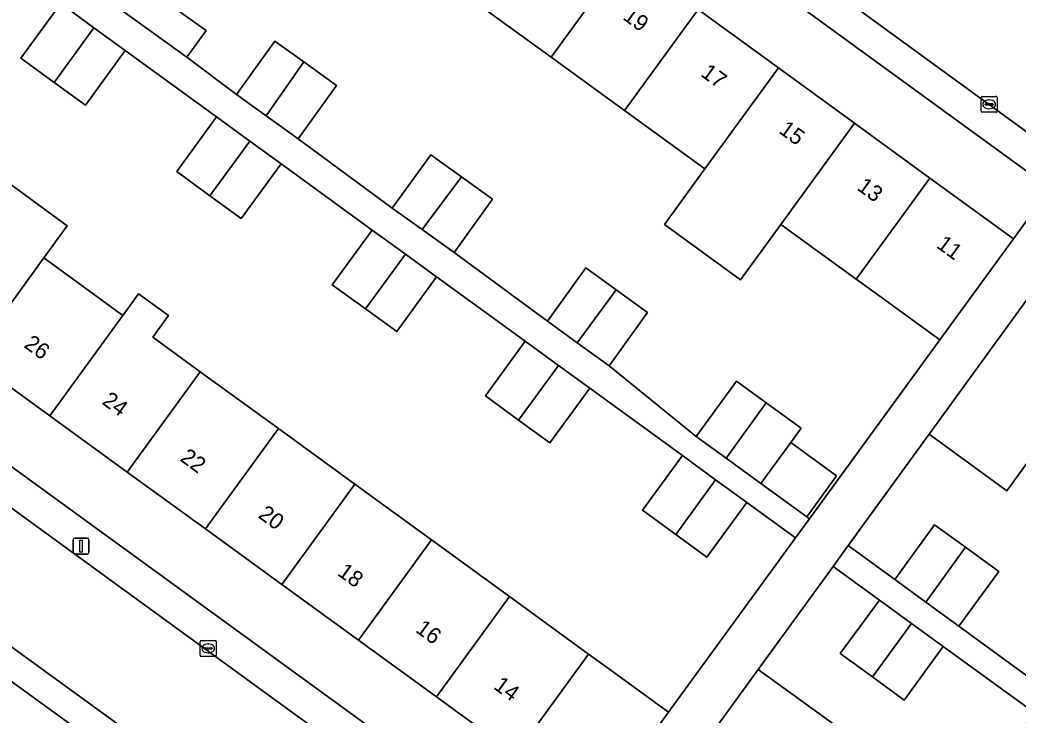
# Model space of a CAD drawing. Extents: x 159674 to 160531, y 382172 to 382904.
# Drawn here: x 160187.9 to 160250.3, y 382582.3 to 382625.8 of the extents above; entities that cross this region are included whole.
import ezdxf

# ---------------------------------------------------------------- set-up
doc = ezdxf.new("R2010")
doc.units = 0
for name, color, linetype in [('IMGEO_Erf', 7, 'Continuous'), ('IMGEO_Kolk', 7, 'Continuous'), ('IMGEO_Lichtmast', 7, 'Continuous'), ('IMGEO_Muur', 7, 'Continuous'), ('IMGEO_Pand', 7, 'Continuous'), ('IMGEO_Pand_nummerreeks', 7, 'Continuous'), ('IMGEO_Rijbaan_lokaal_open', 7, 'Continuous'), ('IMGEO_Voetpad_open', 7, 'Continuous')]:
    doc.layers.add(name, color=color, linetype=linetype)

msp = doc.modelspace()

# ---------------------------------------------------------------- linework, layer by layer
at = {"layer": 'IMGEO_Erf'}
for points in [[(160192.371, 382656.018), (160191.429, 382654.755), (160196.366, 382651.16), (160201.151, 382647.676), (160205.944, 382644.186), (160210.716, 382640.712), (160215.563, 382637.183), (160220.423, 382633.644), (160225.684, 382629.813), (160230.281, 382626.467), (160235.303, 382622.81), (160240.057, 382619.348), (160244.768, 382615.918), (160249.985, 382612.12), (160251.643, 382614.384), (160252.294, 382615.273), (160195.833, 382656.371)], [(160186.03, 382616.426), (160190.83, 382612.935), (160189.362, 382610.917), (160194.303, 382607.323), (160195.291, 382608.68), (160197.157, 382607.322), (160196.17, 382605.965), (160199.139, 382603.805), (160204.031, 382600.247), (160208.807, 382596.773), (160213.603, 382593.285), (160218.472, 382589.743), (160223.426, 382586.14), (160224.383, 382585.444), (160228.427, 382582.503), (160236.364, 382593.408), (160233.316, 382595.626), (160230.826, 382592.207), (160228.873, 382593.629), (160226.796, 382595.141), (160229.286, 382598.56), (160223.493, 382602.771), (160221.003, 382599.352), (160219.051, 382600.773), (160216.973, 382602.286), (160219.463, 382605.705), (160213.921, 382609.733), (160211.431, 382606.314), (160209.478, 382607.736), (160207.401, 382609.248), (160209.891, 382612.667), (160204.193, 382616.809), (160201.703, 382613.39), (160199.752, 382614.81), (160197.673, 382616.324), (160200.163, 382619.743), (160194.452, 382623.894), (160191.962, 382620.475), (160190.009, 382621.897), (160187.932, 382623.409), (160190.422, 382626.828)], [(160196.939, 382626.986), (160199.509, 382625.137), (160198.309, 382623.468), (160201.411, 382621.139), (160203.812, 382624.476), (160205.614, 382623.18), (160207.672, 382621.699), (160205.271, 382618.362), (160211.152, 382614.032), (160213.553, 382617.369), (160215.476, 382615.986), (160217.413, 382614.592), (160215.012, 382611.255), (160220.852, 382606.956), (160223.253, 382610.293), (160225.147, 382608.93), (160227.113, 382607.516), (160224.712, 382604.179), (160230.152, 382599.76), (160232.672, 382603.221), (160234.535, 382601.864), (160236.717, 382600.276), (160236.063, 382599.377), (160238.922, 382597.296), (160237.058, 382594.733), (160237.235, 382594.604), (160245.379, 382605.794), (160241.337, 382608.737), (160240.162, 382609.592), (160235.451, 382613.022), (160232.922, 382609.549), (160228.167, 382613.013), (160230.696, 382616.485), (160225.675, 382620.141), (160221.078, 382623.488), (160215.817, 382627.318)], [(160165.053, 382614.084), (160221.524, 382573.013), (160222.117, 382573.829), (160223.859, 382576.224), (160218.859, 382579.861), (160213.905, 382583.464), (160209.035, 382587.006), (160204.24, 382590.494), (160199.464, 382593.968), (160194.572, 382597.526), (160189.734, 382601.045), (160184.794, 382604.638), (160179.995, 382608.129), (160175.241, 382611.587), (160170.266, 382615.205), (160165.277, 382618.834), (160164.421, 382617.647)], [(160154.946, 382604.626), (160154.192, 382603.615), (160159.129, 382600.024), (160163.793, 382596.632), (160168.857, 382592.948), (160173.849, 382589.318), (160178.531, 382585.912), (160183.495, 382582.302), (160188.238, 382578.852), (160193.235, 382575.218), (160198.086, 382571.689), (160202.822, 382568.244), (160207.751, 382564.659), (160212.767, 382561.011), (160214.457, 382563.306), (160215.141, 382564.235), (160158.66, 382605.256)], [(160259.378, 382589.214), (160261.261, 382591.801), (160256.332, 382595.389), (160251.452, 382598.943), (160249.571, 382596.36), (160244.707, 382599.903), (160239.649, 382592.926), (160242.566, 382590.809), (160245.059, 382594.233), (160246.995, 382592.823), (160249.066, 382591.315), (160246.573, 382587.891), (160252.375, 382583.666), (160254.868, 382587.09), (160256.804, 382585.68), (160258.875, 382584.172), (160256.382, 382580.748), (160259.119, 382578.762), (160261.605, 382582.176), (160266.618, 382578.526), (160267.346, 382578.004), (160271.149, 382583.159)], [(160248.843, 382579.132), (160251.284, 382582.484), (160245.602, 382586.613), (160243.161, 382583.261), (160241.166, 382584.714), (160239.162, 382586.173), (160241.603, 382589.525), (160238.707, 382591.628), (160234.032, 382585.187), (160239.007, 382581.569), (160238.409, 382580.747), (160243.42, 382577.213), (160241.909, 382575.136), (160246.549, 382571.761), (160246.751, 382571.614), (160248.457, 382573.961), (160253.249, 382570.477), (160251.542, 382568.129), (160256.431, 382564.573)]]:
    msp.add_lwpolyline(points, dxfattribs=at)
at = {"layer": 'IMGEO_Kolk'}
for p, q in [((160247.965, 382620.102), (160247.965, 382620.954)), ((160248.04, 382621.028), (160248.892, 382621.028)), ((160248.224, 382620.522), (160248.224, 382620.534)), ((160248.662, 382620.485), (160248.264, 382620.485)), ((160248.267, 382620.571), (160248.665, 382620.571)), ((160248.453, 382620.808), (160248.478, 382620.808)), ((160248.708, 382620.534), (160248.708, 382620.522)), ((160248.966, 382620.954), (160248.966, 382620.102)), ((160248.892, 382620.028), (160248.04, 382620.028)), ((160248.476, 382620.248), (160248.451, 382620.248)), ((160199.143, 382586.076), (160199.143, 382586.928)), ((160199.218, 382587.002), (160200.07, 382587.002)), ((160199.631, 382586.782), (160199.656, 382586.782)), ((160200.144, 382586.928), (160200.144, 382586.076)), ((160199.402, 382586.496), (160199.402, 382586.508)), ((160199.84, 382586.459), (160199.442, 382586.459)), ((160199.445, 382586.545), (160199.843, 382586.545)), ((160199.654, 382586.222), (160199.629, 382586.222)), ((160199.886, 382586.508), (160199.886, 382586.496)), ((160200.07, 382586.002), (160199.218, 382586.002))]:
    msp.add_line(p, q, dxfattribs=at)
for points in [[(160247.965, 382620.102), (160247.965, 382620.954)], [(160248.04, 382621.028), (160248.892, 382621.028)], [(160248.966, 382620.954), (160248.966, 382620.102)], [(160248.892, 382620.028), (160248.04, 382620.028)], [(160199.143, 382586.076), (160199.143, 382586.928)], [(160199.218, 382587.002), (160200.07, 382587.002)], [(160200.144, 382586.928), (160200.144, 382586.076)], [(160200.07, 382586.002), (160199.218, 382586.002)]]:
    msp.add_lwpolyline(points, dxfattribs=at)
for centre, radius, start, end in [((160248.042, 382620.952), 0.0765, 91.55205, 178.44795), ((160248.042, 382620.952), 0.0765, 91.55205, 178.44795), ((160248.264, 382620.531), 0.0403, 85.87752, 175.75265), ((160248.261, 382620.521), 0.0366, 178.93798, 274.71019), ((160248.665, 382620.528), 0.043, 264.86636, 352.45326), ((160248.669, 382620.533), 0.0386, 1.73085, 96.63898), ((160248.89, 382620.952), 0.0765, 1.55205, 88.44795), ((160248.89, 382620.952), 0.0765, 1.55205, 88.44795), ((160248.042, 382620.104), 0.0765, 181.55205, 268.44795), ((160248.042, 382620.104), 0.0765, 181.55205, 268.44795), ((160248.89, 382620.104), 0.0765, 271.55205, 358.44795), ((160248.89, 382620.104), 0.0765, 271.55205, 358.44795), ((160199.22, 382586.926), 0.0765, 91.55205, 178.44795), ((160199.22, 382586.926), 0.0765, 91.55205, 178.44795), ((160200.068, 382586.926), 0.0765, 1.55205, 88.44795), ((160200.068, 382586.926), 0.0765, 1.55205, 88.44795), ((160199.442, 382586.505), 0.0403, 85.87752, 175.75265), ((160199.439, 382586.495), 0.0366, 178.93798, 274.71019), ((160199.843, 382586.502), 0.043, 264.86636, 352.45326), ((160199.847, 382586.507), 0.0386, 1.73085, 96.63898), ((160199.22, 382586.078), 0.0765, 181.55205, 268.44795), ((160199.22, 382586.078), 0.0765, 181.55205, 268.44795), ((160200.068, 382586.078), 0.0765, 271.55205, 358.44795), ((160200.068, 382586.078), 0.0765, 271.55205, 358.44795)]:
    msp.add_arc(centre, radius, start, end, dxfattribs=at)
for centre, major_axis, ratio, start_param, end_param in [((160248.452, 382620.528), (-0.387, 0.002), 0.722429, 4.712389, 7.853982), ((160248.477, 382620.528), (-0.39, 0.002), 0.717154, 1.570796, 4.712389), ((160199.63, 382586.502), (-0.387, 0.002), 0.722429, 4.712389, 7.853982), ((160199.655, 382586.502), (-0.39, 0.002), 0.717154, 1.570796, 4.712389)]:
    msp.add_ellipse(centre, major_axis=major_axis, ratio=ratio, start_param=start_param, end_param=end_param, dxfattribs=at)
at = {"layer": 'IMGEO_Lichtmast'}
for p, q in [((160191.194, 382592.498), (160191.194, 382593.298)), ((160191.194, 382593.298), (160191.194, 382592.498)), ((160191.294, 382593.398), (160192.084, 382593.398)), ((160192.084, 382593.398), (160191.294, 382593.398)), ((160192.184, 382593.298), (160192.184, 382592.498)), ((160192.184, 382592.498), (160192.184, 382593.298)), ((160192.084, 382592.398), (160191.294, 382592.398)), ((160191.294, 382592.398), (160192.084, 382592.398))]:
    msp.add_line(p, q, dxfattribs=at)
msp.add_lwpolyline([(160191.614, 382593.273), (160191.764, 382593.273), (160191.764, 382592.523), (160191.614, 382592.523), (160191.614, 382593.273)], dxfattribs=at)
for centre, start, end in [((160191.294, 382593.298), 90, 180), ((160191.294, 382593.298), 90, 180), ((160192.084, 382593.298), 0, 90), ((160192.084, 382593.298), 360, 90), ((160191.294, 382592.498), 180, 270), ((160191.294, 382592.498), 180, 270), ((160192.084, 382592.498), 270, 0), ((160192.084, 382592.498), 270, 0)]:
    msp.add_arc(centre, 0.1, start, end, dxfattribs=at)
at = {"layer": 'IMGEO_Muur'}
for points in [[(160228.427, 382582.503), (160245.379, 382605.794)], [(160246.587, 382602.485), (160231.976, 382582.36)]]:
    msp.add_lwpolyline(points, dxfattribs=at)
at = {"layer": 'IMGEO_Pand'}
for points in [[(160215.817, 382627.318), (160221.078, 382623.488), (160225.684, 382629.813), (160220.423, 382633.644)], [(160198.139, 382628.654), (160195.931, 382630.243), (160193.551, 382626.891), (160198.309, 382623.468), (160199.509, 382625.137), (160196.939, 382626.986)], [(160230.281, 382626.467), (160225.684, 382629.813), (160221.078, 382623.488), (160225.675, 382620.141)], [(160192.497, 382625.317), (160190.422, 382626.828), (160187.932, 382623.409), (160190.009, 382621.897)], [(160230.281, 382626.467), (160225.675, 382620.141), (160230.696, 382616.485), (160235.303, 382622.81)], [(160192.497, 382625.317), (160190.009, 382621.897), (160191.962, 382620.475), (160194.452, 382623.894)], [(160205.614, 382623.18), (160203.812, 382624.476), (160201.411, 382621.139), (160203.265, 382619.805)], [(160205.614, 382623.18), (160203.265, 382619.805), (160205.271, 382618.362), (160207.672, 382621.699)], [(160240.057, 382619.348), (160235.303, 382622.81), (160230.696, 382616.485), (160228.167, 382613.013), (160232.922, 382609.549), (160235.451, 382613.022)], [(160199.752, 382614.81), (160202.241, 382618.23), (160200.163, 382619.743), (160197.673, 382616.324)], [(160240.162, 382609.592), (160244.768, 382615.918), (160240.057, 382619.348), (160235.451, 382613.022)], [(160199.752, 382614.81), (160201.703, 382613.39), (160204.193, 382616.809), (160202.241, 382618.23)], [(160213.016, 382612.692), (160215.476, 382615.986), (160213.553, 382617.369), (160211.152, 382614.032)], [(160189.362, 382610.917), (160190.83, 382612.935), (160186.03, 382616.426), (160184.562, 382614.408), (160179.995, 382608.129), (160184.794, 382604.638)], [(160213.016, 382612.692), (160215.012, 382611.255), (160217.413, 382614.592), (160215.476, 382615.986)], [(160240.162, 382609.592), (160241.337, 382608.737), (160245.379, 382605.794), (160249.985, 382612.12), (160244.768, 382615.918)], [(160209.478, 382607.736), (160211.966, 382611.156), (160209.891, 382612.667), (160207.401, 382609.248)], [(160209.478, 382607.736), (160211.431, 382606.314), (160213.921, 382609.733), (160211.966, 382611.156)], [(160194.303, 382607.323), (160189.362, 382610.917), (160184.794, 382604.638), (160189.734, 382601.045)], [(160222.713, 382605.617), (160225.147, 382608.93), (160223.253, 382610.293), (160220.852, 382606.956)], [(160199.139, 382603.805), (160196.17, 382605.965), (160197.157, 382607.322), (160195.291, 382608.68), (160194.303, 382607.323), (160189.734, 382601.045), (160194.572, 382597.526)], [(160222.713, 382605.617), (160224.712, 382604.179), (160227.113, 382607.516), (160225.147, 382608.93)], [(160256.003, 382605.192), (160251.138, 382608.735), (160246.587, 382602.485), (160244.707, 382599.903), (160249.571, 382596.36), (160251.452, 382598.943)], [(160221.539, 382604.194), (160219.463, 382605.705), (160216.973, 382602.286), (160219.051, 382600.773)], [(160199.464, 382593.968), (160204.031, 382600.247), (160199.139, 382603.805), (160194.572, 382597.526)], [(160221.539, 382604.194), (160219.051, 382600.773), (160221.003, 382599.352), (160223.493, 382602.771)], [(160232.015, 382598.403), (160234.535, 382601.864), (160232.672, 382603.221), (160230.152, 382599.76)], [(160236.063, 382599.377), (160236.717, 382600.276), (160234.535, 382601.864), (160232.015, 382598.403), (160234.197, 382596.815)], [(160204.24, 382590.494), (160208.807, 382596.773), (160204.031, 382600.247), (160199.464, 382593.968)], [(160236.063, 382599.377), (160234.197, 382596.815), (160237.058, 382594.733), (160238.922, 382597.296)], [(160231.361, 382597.049), (160229.286, 382598.56), (160226.796, 382595.141), (160228.873, 382593.629)], [(160204.24, 382590.494), (160209.035, 382587.006), (160213.603, 382593.285), (160208.807, 382596.773)], [(160231.361, 382597.049), (160228.873, 382593.629), (160230.826, 382592.207), (160233.316, 382595.626)], [(160246.995, 382592.823), (160245.059, 382594.233), (160242.566, 382590.809), (160244.502, 382589.399)], [(160218.472, 382589.743), (160213.603, 382593.285), (160209.035, 382587.006), (160213.905, 382583.464)], [(160246.995, 382592.823), (160244.502, 382589.399), (160246.573, 382587.891), (160249.066, 382591.315)], [(160223.426, 382586.14), (160218.472, 382589.743), (160213.905, 382583.464), (160218.859, 382579.861)], [(160241.166, 382584.714), (160243.605, 382588.067), (160241.603, 382589.525), (160239.162, 382586.173)], [(160241.166, 382584.714), (160243.161, 382583.261), (160245.602, 382586.613), (160243.605, 382588.067)], [(160223.426, 382586.14), (160218.859, 382579.861), (160223.859, 382576.224), (160228.427, 382582.503), (160224.383, 382585.444)], [(160236.868, 382578.802), (160236.951, 382578.742), (160238.409, 382580.747), (160239.007, 382581.569), (160234.032, 382585.187), (160231.976, 382582.36), (160227.395, 382576.062), (160232.288, 382572.503)]]:
    msp.add_lwpolyline(points, close=True, dxfattribs=at)
at = {"layer": 'IMGEO_Rijbaan_lokaal_open'}
msp.add_lwpolyline([(160228.441, 382635.114), (160233.343, 382631.547), (160271.282, 382603.905), (160275.313, 382609.447), (160237.31, 382637.088), (160232.457, 382640.629)], close=True, dxfattribs=at)
for points in [[(160140.763, 382629.192), (160140.555, 382629.351), (160136.439, 382623.587), (160136.712, 382623.379), (160240.412, 382548.029)], [(160245.716, 382552.786), (160140.763, 382629.192)]]:
    msp.add_lwpolyline(points, dxfattribs=at)
at = {"layer": 'IMGEO_Voetpad_open'}
for points in [[(160195.833, 382656.371), (160252.294, 382615.273), (160251.643, 382614.384), (160253.992, 382612.685), (160276.843, 382596.162)], [(160278.047, 382598.976), (160273.601, 382602.215), (160271.282, 382603.905), (160233.343, 382631.547), (160228.441, 382635.114), (160226.048, 382636.856)], [(160140.555, 382629.351), (160140.763, 382629.192), (160245.716, 382552.786)], [(160190.422, 382626.828), (160192.497, 382625.317), (160194.452, 382623.894), (160200.163, 382619.743), (160202.241, 382618.23), (160204.193, 382616.809), (160209.891, 382612.667), (160211.966, 382611.156), (160213.921, 382609.733), (160219.463, 382605.705), (160221.539, 382604.194), (160223.493, 382602.771), (160229.286, 382598.56), (160231.361, 382597.049), (160233.316, 382595.626), (160236.364, 382593.408), (160237.235, 382594.604), (160237.058, 382594.733), (160234.197, 382596.815), (160232.015, 382598.403), (160230.152, 382599.76), (160224.712, 382604.179), (160222.713, 382605.617), (160220.852, 382606.956), (160215.012, 382611.255), (160213.016, 382612.692), (160211.152, 382614.032), (160205.271, 382618.362), (160203.265, 382619.805), (160201.411, 382621.139), (160198.309, 382623.468), (160193.551, 382626.891)], [(160240.412, 382548.029), (160136.712, 382623.379)], [(160222.117, 382573.829), (160221.524, 382573.013), (160165.053, 382614.084)], [(160158.66, 382605.256), (160215.141, 382564.235), (160214.457, 382563.306), (160216.898, 382561.575), (160239.728, 382544.943)]]:
    msp.add_lwpolyline(points, dxfattribs=at)
for points in [[(160244.707, 382599.903), (160246.587, 382602.485), (160251.138, 382608.735), (160253.992, 382612.685), (160251.643, 382614.384), (160249.985, 382612.12), (160245.379, 382605.794), (160237.235, 382594.604), (160236.364, 382593.408), (160228.427, 382582.503), (160223.859, 382576.224), (160222.117, 382573.829), (160224.48, 382572.038), (160227.395, 382576.062), (160231.976, 382582.36), (160234.032, 382585.187), (160238.707, 382591.628), (160239.649, 382592.926)], [(160246.573, 382587.891), (160244.502, 382589.399), (160242.566, 382590.809), (160239.649, 382592.926), (160238.707, 382591.628), (160241.603, 382589.525), (160243.605, 382588.067), (160245.602, 382586.613), (160251.284, 382582.484), (160253.286, 382581.026), (160255.283, 382579.572), (160258.248, 382577.474), (160263.256, 382573.828), (160264.132, 382575.112), (160259.119, 382578.762), (160256.382, 382580.748), (160254.311, 382582.256), (160252.375, 382583.666)]]:
    msp.add_lwpolyline(points, close=True, dxfattribs=at)

# ---------------------------------------------------------------- texts
at = {"layer": 'IMGEO_Pand_nummerreeks'}
for s, rotation, p in [('19', 323.9414, (160225.501, 382625.89)), ('17', 323.9414, (160230.38, 382622.337)), ('15', 323.94377, (160235.26, 382618.783)), ('13', 323.9414, (160240.14, 382615.231)), ('11', 323.9414, (160245.112, 382611.611)), ('26', 323.96949, (160188.059, 382605.378)), ('24', 323.96668, (160192.941, 382601.829)), ('22', 323.96949, (160197.82, 382598.279)), ('20', 323.96949, (160202.707, 382594.725)), ('18', 323.96949, (160207.662, 382591.12)), ('16', 323.96949, (160212.541, 382587.571)), ('14', 323.96949, (160217.423, 382584.02))]:
    msp.add_text(s, height=1, rotation=rotation, dxfattribs=at).set_placement(p)

doc.saveas('drawing.dxf')
